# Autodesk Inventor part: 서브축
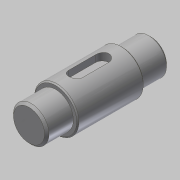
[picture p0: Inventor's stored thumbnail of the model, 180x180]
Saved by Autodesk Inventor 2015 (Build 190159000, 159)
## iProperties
Created: 2019-03
Part Number: 서브축
Material: 강철, 연강
Document SubType Name: Modeling
Designer: mduedu
Density: 1 g/cm^3
Appearance: 강철
Author: mduedu
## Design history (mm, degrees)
sketch "스케치1"
  geometry: L1 (0, 0)-(12, 0); L2 (12, 0)-(12, 8); L3 (12, 8)-(0, 8); L4 (0, 8)-(0, 0); L5 (12, 0)-(42, 0); L6 (42, 0)-(42, 10); L7 (42, 10)-(12, 10); L8 (12, 10)-(12, 0); L9 (42, 0)-(55, 0); L10 (55, 0)-(55, 8); L11 (55, 8)-(42, 8); L12 (42, 8)-(42, 0)
  constraints: 24 end point, 6 parallel, 3 horizontal, 3 perpendicular
  dimensions: "d0" = 16 diameter of L3 L1; "d2" = 20 diameter of L7 L5; "d3" = 16 diameter of L11 L9; "d4" = 12 distance of L2.end L3.end; "d5" = 30 distance of L6.end L7.end; "d6" = 55 distance between parallel lines of L10 L4
revolve "회전1" sketch "스케치1" stored, may be unused: angle "d7" = 90 deg
node "작업 평면1"
sketch "스케치2" dims "d10" = 18
  geometry: L1 (6, -3)-(-6, -3); L2 (-6, -3)-(-6, 3); L3 (-6, 3)-(6, 3); L4 (6, 3)-(6, -3); L5 (15, 10)-(15, -10) reference; 3 further points
  constraints: 8 end point, 2 midpoint, 2 parallel, 2 vertical alignment, 1 horizontal, 1 horizontal alignment, 1 perpendicular, 4 other
  dimensions: "d8" = 6 distance between parallel lines of L3 L1; "d11" = 6 dimension on L5
extrude "돌출1" cut sketch "스케치2" distance "d12" = 3.5; taper "d13" = 0 deg
chamfer "모따기1" distance "d14" = 1; stored, may be unused: second distance "d15" = 2, angle "d16" = 45 deg
chamfer "모따기2" distance "d17" = 0.5; stored, may be unused: second distance "d18" = 2, angle "d19" = 45 deg
node "솔리드1"
